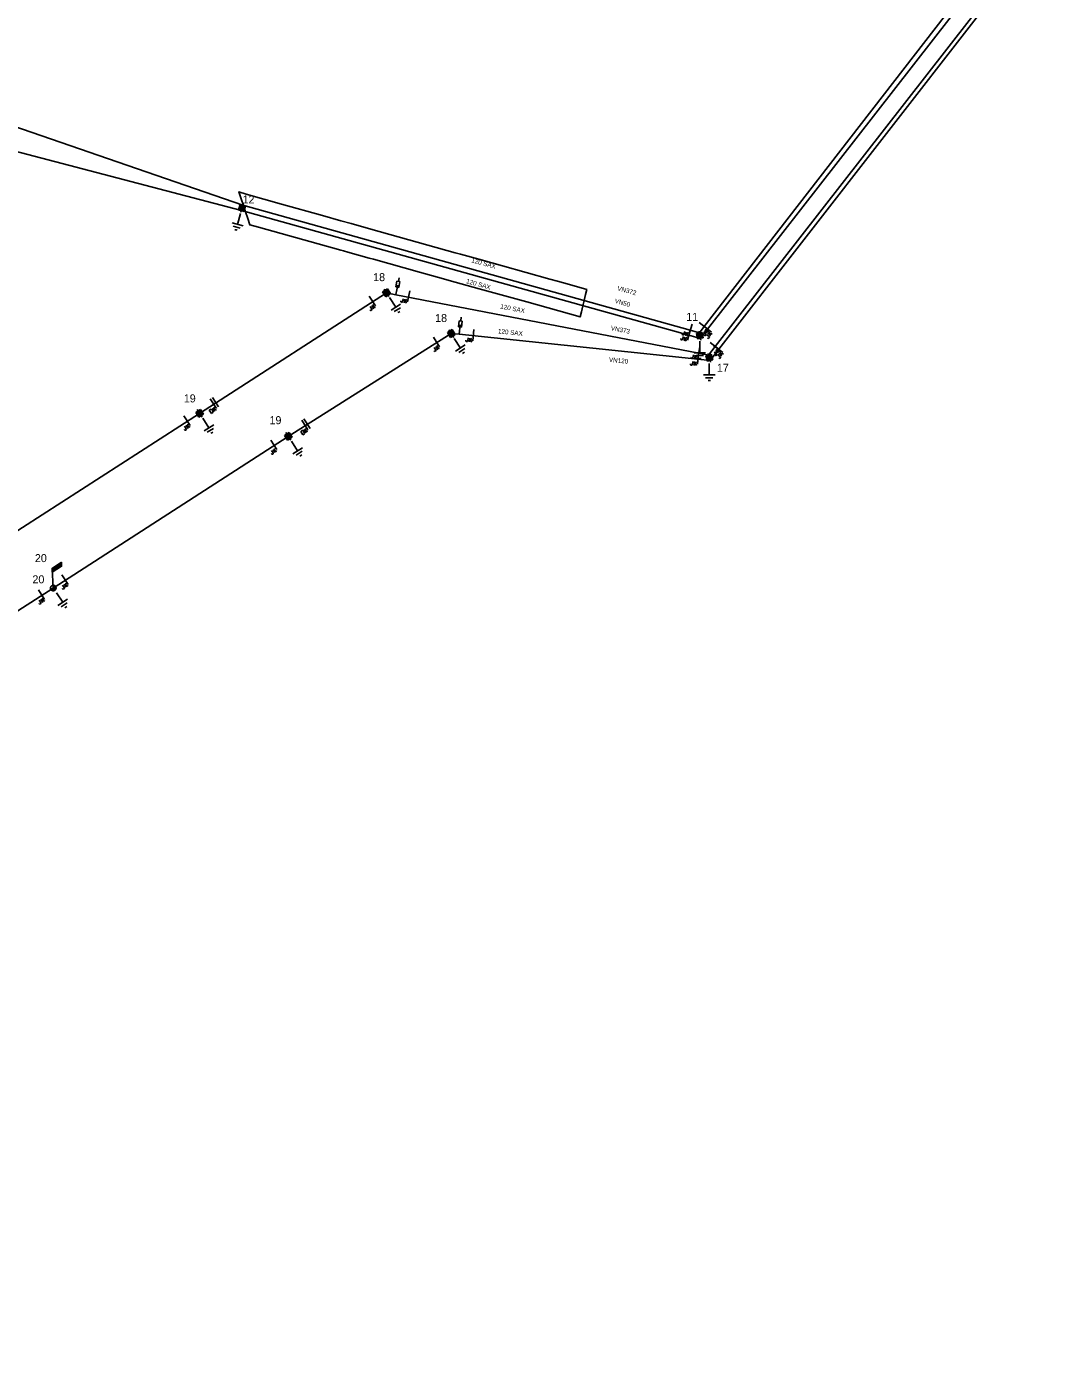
# Model space of a CAD drawing. Extents: x -540879 to -537255, y -1184046 to -1180016.
# Drawn here: x -538756.2 to -538529.1, y -1180900.2 to -1180611.6 of the extents above; entities that cross this region are included whole.
import ezdxf

# ---------------------------------------------------------------- set-up
doc = ezdxf.new("R2010")
doc.units = 0
for name, color, linetype in [('Default', 7, 'Continuous'), ('Vrstva 1', 7, 'Continuous'), ('Vrstva 11', 7, 'Continuous'), ('Vrstva 12', 7, 'Continuous'), ('Vrstva 13', 7, 'Continuous'), ('Vrstva 14', 7, 'Continuous'), ('Vrstva 15', 7, 'Continuous'), ('Vrstva 16', 7, 'Continuous'), ('Vrstva 18', 7, 'Continuous'), ('Vrstva 2', 7, 'Continuous'), ('Vrstva 3', 7, 'Continuous'), ('Vrstva 35', 7, 'Continuous')]:
    doc.layers.add(name, color=color, linetype=linetype)

# ---------------------------------------------------------------- blocks, each defined once
blk = doc.blocks.new('VN850')
at = {"layer": 'Vrstva 15'}
for points in [[(-0.56, 1.43), (-0.56, -1.07)], [(-0.01, 1.43), (-0.01, -1.07)], [(-2.09, -0.54), (-1.78, -0.54)], [(-2.09, -1.41), (-2.09, -0.54)], [(-1.78, -1.41), (-2.09, -1.41)], [(-1.78, -0.54), (-1.66, -0.6)], [(-1.67, -1.35), (-1.78, -1.41)], [(-1.59, -1.2), (-1.67, -1.35)], [(-1.66, -0.6), (-1.59, -0.75)], [(-1.59, -0.75), (-1.55, -0.96)], [(-1.55, -0.96), (-1.59, -1.2)], [(-1.26, -0.54), (-1.26, -1.41)], [(-0.85, -0.54), (-1.26, -1.09)], [(-1.13, -0.92), (-0.77, -1.41)]]:
    blk.add_lwpolyline(points, dxfattribs=at)
blk = doc.blocks.new('VN840')
at = {"layer": 'Vrstva 15'}
for points in [[(-0.01, 1.41), (-0.01, -1.09)], [(-1.51, -1.24), (-1.51, -1.15)], [(-1.48, -1.35), (-1.51, -1.24)], [(-1.33, -1.42), (-1.48, -1.35)], [(-1.27, -1.42), (-1.33, -1.42)], [(-1.13, -1.35), (-1.27, -1.42)], [(-1.09, -1.24), (-1.13, -1.35)], [(-1.09, -0.59), (-1.09, -1.24)], [(-0.68, -0.59), (-0.68, -1.42)], [(-0.68, -1.11), (-0.27, -0.59)], [(-0.54, -0.94), (-0.2, -1.42)]]:
    blk.add_lwpolyline(points, dxfattribs=at)
blk = doc.blocks.new('VN440')
at = {"layer": 'Vrstva 2'}
for points in [[(1.22, 0), (1.21, 0.13), (1.19, 0.25), (1.16, 0.38), (1.11, 0.5), (1.05, 0.61), (0.98, 0.72), (0.9, 0.82), (0.81, 0.91), (0.71, 0.99), (0.6, 1.06), (0.49, 1.12), (0.37, 1.16), (0.25, 1.2), (0.12, 1.22), (-0.01, 1.22), (-0.14, 1.22), (-0.26, 1.2), (-0.39, 1.16), (-0.51, 1.12), (-0.62, 1.06), (-0.73, 0.99), (-0.83, 0.91), (-0.92, 0.82), (-1, 0.72), (-1.07, 0.61), (-1.13, 0.5), (-1.18, 0.38), (-1.21, 0.25), (-1.23, 0.13), (-1.24, 0), (-1.23, -0.13), (-1.21, -0.26), (-1.18, -0.38), (-1.13, -0.5), (-1.07, -0.62), (-1, -0.73), (-0.92, -0.83), (-0.83, -0.92), (-0.73, -1), (-0.62, -1.07), (-0.51, -1.13), (-0.39, -1.17), (-0.26, -1.2), (-0.14, -1.23), (-0.01, -1.23), (0.12, -1.23), (0.25, -1.2), (0.37, -1.17), (0.49, -1.13), (0.6, -1.07), (0.71, -1), (0.81, -0.92), (0.9, -0.83), (0.98, -0.73), (1.05, -0.62), (1.11, -0.5), (1.16, -0.38), (1.19, -0.26), (1.21, -0.13), (1.22, 0)], [(-1.24, 0), (1.22, 0)], [(-1.18, -0.34), (1.1, -0.34)], [(-1.01, -0.63), (0.97, -0.63)], [(-0.74, -0.92), (0.68, -0.92)]]:
    blk.add_lwpolyline(points, dxfattribs=at)
blk = doc.blocks.new('VN820')
at = {"layer": 'Vrstva 13'}
for points in [[(0, 0), (0, -2.1)], [(-0.32, -1.63), (0.34, -1.63)], [(-0.32, -2.95), (-0.32, -1.63)], [(0, -2.1), (-0.12, -1.86)], [(0, -2.1), (0.12, -1.86)], [(0.34, -1.63), (0.34, -2.95)], [(0.34, -2.95), (-0.32, -2.95)], [(0, -2.95), (0, -3.75)]]:
    blk.add_lwpolyline(points, dxfattribs=at)
blk = doc.blocks.new('VN810')
at = {"layer": 'Vrstva 14'}
for points in [[(0, -1.25), (0, -3.75)], [(1.25, -3.75), (-1.25, -3.75)], [(0.77, -4.37), (-0.8, -4.37)], [(0, -5), (-0.25, -5)], [(0.27, -5), (0, -5)]]:
    blk.add_lwpolyline(points, dxfattribs=at)
blk = doc.blocks.new('VN001')
at = {"layer": 'Default'}
for p, q in [((1.73, 3.03), (4.14, 3.03)), ((1.76, 3.08), (4.17, 3.08)), ((1.79, 3.13), (4.2, 3.13)), ((1.82, 3.18), (4.23, 3.18)), ((1.85, 3.23), (4.26, 3.23)), ((1.87, 3.28), (4.29, 3.28)), ((1.9, 3.33), (4.32, 3.33)), ((1.93, 3.38), (4.35, 3.38)), ((1.96, 3.43), (4.37, 3.43)), ((1.99, 3.48), (4.4, 3.48)), ((2.02, 3.53), (4.43, 3.53)), ((2.05, 3.58), (4.46, 3.58)), ((2.07, 3.63), (4.49, 3.63)), ((2.1, 3.68), (4.52, 3.68)), ((2.13, 3.73), (2.54, 3.73))]:
    blk.add_line(p, q, dxfattribs=at)
blk.add_lwpolyline([(2.13, 3.73), (0, 0)], dxfattribs=at)
blk.add_lwpolyline([(4.55, 3.73), (2.13, 3.73), (1.7, 2.98), (4.12, 2.99)], close=True, dxfattribs=at)
blk = doc.blocks.new('VN470')
at = {"layer": 'Vrstva 2'}
for points in [[(-1.23, 1.22), (1.23, 1.22)], [(-1.23, -1.23), (-1.23, 1.22)], [(-0.92, 0.9), (0.92, 0.9)], [(-0.92, -0.95), (-0.92, 0.9)], [(-0.61, 0.61), (0.61, 0.61)], [(-0.61, -0.62), (-0.61, 0.61)], [(-0.31, -0.27), (-0.31, 0.34)], [(-0.31, 0.34), (0.31, 0.34)], [(0, 1.22), (0, 1.97)], [(0.31, 0.34), (0.31, -0.27)], [(0.61, 0.61), (0.61, -0.62)], [(0.92, 0.9), (0.92, -0.95)], [(1.23, 1.22), (1.23, -1.23)], [(1.23, -1.23), (-1.23, -1.23)], [(0.92, -0.95), (-0.92, -0.95)], [(0.61, -0.62), (-0.61, -0.62)], [(0.31, -0.27), (-0.31, -0.27)], [(0, -1.23), (0, -1.98)]]:
    blk.add_lwpolyline(points, dxfattribs=at)

msp = doc.modelspace()

# ---------------------------------------------------------------- linework, layer by layer
at = {"layer": 'Vrstva 1'}
for points in [[(-538763.41, -1180637.58), (-538761.55, -1180638.07), (-538760.78, -1180638.27), (-538758.95, -1180638.76), (-538709.24, -1180651.86), (-538611.41, -1180679.1), (-538608.89, -1180679.8), (-538607.32, -1180677.78), (-538533.8, -1180583.25), (-538532.49, -1180581.57), (-538530.42, -1180580.29), (-538435.45, -1180522.72)], [(-538780.03, -1180626.12), (-538778.54, -1180626.64), (-538777.41, -1180627.03), (-538776.14, -1180627.46), (-538708.94, -1180650.67), (-538611.11, -1180678.01), (-538609.12, -1180678.56), (-538608.05, -1180677.18), (-538534.75, -1180582.52), (-538533.61, -1180581.05), (-538532.85, -1180581.05)], [(-538677.51, -1180669.82), (-538675.45, -1180670.23), (-538609.25, -1180683.03), (-538607.12, -1180683.42), (-538605.66, -1180681.55), (-538531.67, -1180586.46), (-538530.04, -1180584.37)], [(-538529.21, -1180584.68), (-538530.57, -1180586.43), (-538604.89, -1180682.17), (-538606.79, -1180684.61), (-538609.45, -1180684.35), (-538661.61, -1180678.9), (-538663.36, -1180678.72)], [(-538677.51, -1180669.82), (-538718.36, -1180696.18), (-538761.4, -1180723.93)], [(-538663.36, -1180678.72), (-538698.99, -1180701.21), (-538750.35, -1180734.36)], [(-538750.35, -1180734.36), (-538806.1, -1180770.08), (-538886.12, -1180821.54), (-538931.61, -1180850.77), (-539020.62, -1180908.27), (-539099.07, -1180958.39), (-539182.51, -1181012.88)]]:
    msp.add_lwpolyline(points, dxfattribs=at)
at = {"layer": 'Vrstva 35'}
msp.add_lwpolyline([(-538708.2, -1180648.28), (-538700.45, -1180650.45), (-538691.51, -1180652.94), (-538687.5, -1180654.06), (-538685.27, -1180654.69), (-538680.91, -1180655.91), (-538662.5, -1180661.05), (-538661.37, -1180661.37), (-538657.31, -1180662.5), (-538641.83, -1180666.83), (-538640.14, -1180667.3), (-538637.5, -1180668.04), (-538633.76, -1180669.08), (-538634.03, -1180670.21), (-538634.34, -1180671.52), (-538634.61, -1180672.64), (-538634.92, -1180673.95), (-538635.19, -1180675.08), (-538637.5, -1180674.43), (-538646.84, -1180671.83), (-538657.28, -1180668.93), (-538662.5, -1180667.47), (-538666.39, -1180666.39), (-538670.34, -1180665.29), (-538680.36, -1180662.5), (-538681.29, -1180662.24), (-538685.95, -1180660.95), (-538686.94, -1180660.67), (-538687.5, -1180660.51), (-538705.5, -1180655.5), (-538707.4, -1180654.97), (-538707.86, -1180653.56), (-538708.33, -1180652.12), (-538708.8, -1180650.71), (-538709.27, -1180649.27), (-538709.77, -1180647.74)], close=True, dxfattribs=at)

# ---------------------------------------------------------------- block references
at = {"layer": 'Vrstva 11', "rotation": 33.2653498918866}
msp.add_blockref('VN001', (-538750.35, -1180734.35), dxfattribs=at)
at = {"layer": 'Vrstva 13'}
for name, p, xscale, yscale, rotation in [('VN470', (-538709.09, -1180651.26), 0.5, 0.5000000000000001, 164.54417775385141), ('VN470', (-538677.51, -1180669.82), 0.5, 0.5000000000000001, 32.83342772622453), ('VN470', (-538663.36, -1180678.72), 0.5000000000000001, 0.4999999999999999, 32.264430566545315), ('VN470', (-538609.01, -1180679.18), 0.5000000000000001, 0.4999999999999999, -169.73215545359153), ('VN470', (-538606.96, -1180684.02), 0.5, 0.5, -164.38176118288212), ('VN470', (-538718.36, -1180696.18), 0.5, 0.5, 32.80638615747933), ('VN470', (-538698.99, -1180701.21), 0.5000000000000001, 0.4999999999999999, 32.838186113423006), ('VN440', (-538750.35, -1180734.36), 0.5, 0.5000000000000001, 32.83794171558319)]:
    msp.add_blockref(name, p, dxfattribs=dict(at, xscale=xscale, yscale=yscale, rotation=rotation))
at = {"layer": 'Vrstva 15'}
for p, rotation in [((-538709.09, -1180651.26), -15.182183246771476), ((-538677.51, -1180669.82), 32.83342776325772), ((-538663.36, -1180678.72), 32.26372212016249), ((-538609.01, -1180679.18), -0.15294177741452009), ((-538718.36, -1180696.18), 32.39088618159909), ((-538698.99, -1180701.21), 32.83818622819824), ((-538750.35, -1180734.35), 33.265350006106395)]:
    msp.add_blockref('VN810', p, dxfattribs=dict(at, rotation=rotation))
msp.add_blockref('VN810', (-538606.96, -1180684.02), dxfattribs=at)
at = {"layer": 'Vrstva 16'}
for p, rotation in [((-538675.45, -1180670.21), 169.17956112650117), ((-538661.61, -1180678.9), 173.79944157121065)]:
    msp.add_blockref('VN820', p, dxfattribs=dict(at, rotation=rotation))
at = {"layer": 'Vrstva 18'}
for name, p, rotation in [('VN840', (-538680.5, -1180671.75), 32.83342772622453), ('VN840', (-538672.7, -1180670.76), -10.93883063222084), ('VN840', (-538611.11, -1180678.01), -15.614244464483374), ('VN840', (-538608.05, -1180677.18), 52.24555556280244), ('VN840', (-538658.55, -1180679.22), -5.96108051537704), ('VN840', (-538611.41, -1180679.1), -15.557438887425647), ('VN840', (-538607.32, -1180677.78), 52.12756113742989), ('VN840', (-538666.5, -1180680.7), 32.26372219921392), ('VN840', (-538609.25, -1180683.03), -10.551524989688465), ('VN840', (-538605.66, -1180681.55), 52.113125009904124), ('VN840', (-538604.89, -1180682.17), 52.17880006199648), ('VN840', (-538609.45, -1180684.35), -5.678211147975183), ('VN850', (-538714.8, -1180693.88), 32.83342772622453), ('VN840', (-538721.04, -1180697.91), 32.806888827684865), ('VN850', (-538694.78, -1180698.55), 32.26372219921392), ('VN840', (-538702.06, -1180703.19), 32.83794171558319), ('VN840', (-538747.71, -1180732.65), 32.8379417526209), ('VN840', (-538752.82, -1180735.94), 32.6519832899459)]:
    msp.add_blockref(name, p, dxfattribs=dict(at, rotation=rotation))

# ---------------------------------------------------------------- texts
at = {"layer": 'Vrstva 12'}
msp.add_text('20', height=1.75, dxfattribs=at).set_placement((-538754.37, -1180728.7))
at = {"layer": 'Vrstva 14'}
for s, p in [('12', (-538708.98, -1180650.29)), ('18', (-538680.44, -1180667.27)), ('18', (-538666.89, -1180676.21)), ('11', (-538612.01, -1180675.95)), ('17', (-538605.31, -1180687.09)), ('19', (-538721.82, -1180693.78)), ('19', (-538703.09, -1180698.54)), ('20', (-538754.91, -1180733.34))]:
    msp.add_text(s, height=1.75, dxfattribs=at).set_placement(p)
at = {"layer": 'Vrstva 2'}
for rotation, p in [(344.386, (-538659.06, -1180663.12)), (344.442, (-538660.18, -1180667.69)), (349.061, (-538652.72, -1180673.23)), (354.039, (-538653.2, -1180678.68))]:
    msp.add_text('120 SAX', height=1, rotation=rotation, dxfattribs=at).set_placement(p)
at = {"layer": 'Vrstva 3'}
for s, rotation, p in [('VN372', 344.386, (-538627.13, -1180669.25)), ('VN50', 344.442, (-538627.73, -1180672.01)), ('VN373', 349.061, (-538628.55, -1180677.98)), ('VN120', 354.039, (-538628.94, -1180684.89))]:
    msp.add_text(s, height=1, rotation=rotation, dxfattribs=at).set_placement(p)

doc.saveas('drawing.dxf')
